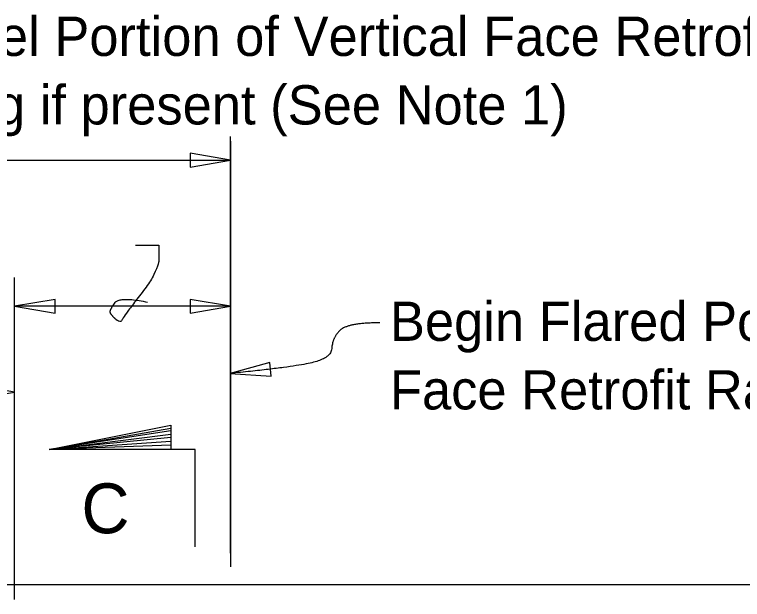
# Model space of a CAD drawing. Extents: x 1.5 to 68.7, y 0 to 31.1.
# Drawn here: x 6.295 to 10.034, y 13.743 to 16.745 of the extents above; entities that cross this region are included whole.
import ezdxf

# ---------------------------------------------------------------- set-up
doc = ezdxf.new("R2010")
doc.units = 0
for name, color, linetype in [('AdhocPoint_dp', 7, 'Continuous'), ('PlotBorder_dp', 7, 'Continuous'), ('SheetBorder_dp', 7, 'Continuous')]:
    doc.layers.add(name, color=color, linetype=linetype)

msp = doc.modelspace()

# ---------------------------------------------------------------- linework, layer by layer
at = {"layer": 'AdhocPoint_dp'}
for p, q in [((7.4053, 13.981), (7.4053, 16.1198)), ((7.4052, 16.0948), (7.4052, 13.9093)), ((6.2955, 13.7426), (6.2955, 15.3961)), ((7.4053, 15.2478), (6.2955, 15.2478)), ((6.4727, 14.5119), (7.0977, 14.6219)), ((7.0977, 14.6085), (6.4727, 14.5119)), ((6.4727, 14.5119), (7.0977, 14.5919)), ((7.0977, 14.5735), (6.4727, 14.5119)), ((6.4727, 14.5119), (7.0977, 14.5552)), ((7.0977, 14.5352), (6.4727, 14.5119))]:
    msp.add_line(p, q, dxfattribs=at)
for points in [[(7.4053, 15.9978), (7.197, 16.0331), (7.197, 15.9626)], [(6.2955, 15.2478), (6.5037, 15.2126), (6.5037, 15.2831)], [(7.4053, 15.2478), (7.197, 15.2831), (7.197, 15.2126)], [(7.4031, 14.903), (7.6138, 14.8883), (7.6069, 14.9585)], [(6.2955, 14.8073), (6.0872, 14.8426), (6.0872, 14.772)]]:
    msp.add_lwpolyline(points, close=True, dxfattribs=at)
for points in [[(3.8717, 15.9978), (7.4052, 15.9978)], [(7.2227, 14.0119), (7.2227, 14.5119), (6.4727, 14.5119), (7.0977, 14.6369), (7.0977, 14.5119)]]:
    msp.add_lwpolyline(points, dxfattribs=at)
for points in [[(6.9159, 15.5612), (7.0366, 15.5612), (7.0366, 15.5612), (7.0366, 15.4286), (6.8564, 15.1975), (6.8394, 15.1584), (6.7867, 15.2077), (6.7867, 15.2315), (6.8343, 15.2995), (6.9788, 15.2689)], [(8.1719, 15.1629), (8.0057, 15.1629), (7.9277, 15.0849), (7.9225, 14.9809), (7.7199, 14.9341), (7.403, 14.903)]]:
    msp.add_open_spline(points, degree=2, dxfattribs=at)
at = {"layer": 'PlotBorder_dp'}
msp.add_line((14.1461, 13.8178), (3.8717, 13.8178), dxfattribs=at)

# ---------------------------------------------------------------- texts
at = {"layer": 'AdhocPoint_dp'}
for s, p in [('Parallel Portion of Vertical Face Retrofit ', (5.5257, 16.5332)), ('Railing if present (See Note 1)', (5.5257, 16.1812)), ('Begin Flared Portion of Vertical ', (8.2235, 15.0701)), ('Face Retrofit Railing', (8.2235, 14.7181))]:
    msp.add_text(s, height=0.2016, dxfattribs=at).set_placement(p)
at = {"layer": 'SheetBorder_dp'}
msp.add_text('C', height=0.256, dxfattribs=at).set_placement((6.6388, 14.0824))

doc.saveas('drawing.dxf')
